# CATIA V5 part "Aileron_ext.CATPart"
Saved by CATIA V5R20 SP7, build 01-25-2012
Part number: Aileron_ext
Bounding box of the stored display mesh (mm): x -250 to 250, y -11.888 to 90.046, z 87.725 to 130.883
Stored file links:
  F:\Travaux\Modélisations\CFAO_2011\MMS\MMS_GR2\AA_OK\tquattrone\Catia\Aileron_ext.CATPart
  F:\Travaux\Modélisations\CFAO_2011\MMS\MMS_GR2\AA_OK\tquattrone\Catia\Squelette.CATPart
  C:\Users\Tom\Documents\Cours 2A\CFAO\Projet thinkmotion\Aileron_citroen.CATProduct
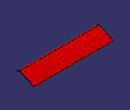
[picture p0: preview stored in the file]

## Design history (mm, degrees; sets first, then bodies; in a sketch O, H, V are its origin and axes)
Set1
  Plane1 "Plan_bout": linked copy from another document
  Line1 "Courbe_guide": linked copy from another document
  Plane2 "Plan_sym": linked copy from another document
Body1 (main body)
  Sketch1 on Plane1, origin (250, 0, 0), H (0, 1, 0), V (0, 0, 1)
    spline S1 through (3.0467, 130.17) (25.7368, 121.2153) (79.7886, 95.9331) (89.1829, 90.1753) (90.0782, 88.2476) (87.9664, 85.0955) (85.3809, 84.421) (80.5377, 84.5079) (32.5277, 89.1475) (2.9781, 102.2718) (-8.4275, 114.0611) (-11.8883, 120.6154) (-8.9489, 128.303)
    point P1 (57.069, 107.6883)
    point P2 (65.6176, 84.6979)
    coincidence: P1 S1, P2 S1
  Rib1: profile Sketch1, centre curve Line1, thin wall 2
  Sketch2 on Plane1, origin (250, 0, 0), H (0, 1, 0), V (0, 0, 1)
    line L1 (-8.7337, 119.9187) -> (95.5355, 85.9357)
    line L2 (95.5355, 85.9357) -> (70.6317, 75.1912)
    line L3 (70.6317, 75.1912) -> (-33.6375, 109.1742)
    line L4 (-33.6375, 109.1742) -> (-8.7337, 119.9187)
    parallelism: L4 L2, L1 L3
  Pocket1: profile Sketch2, direction (-1, 0, 0), up to Plane2
  Mirror1: of the body so far, about Plane2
